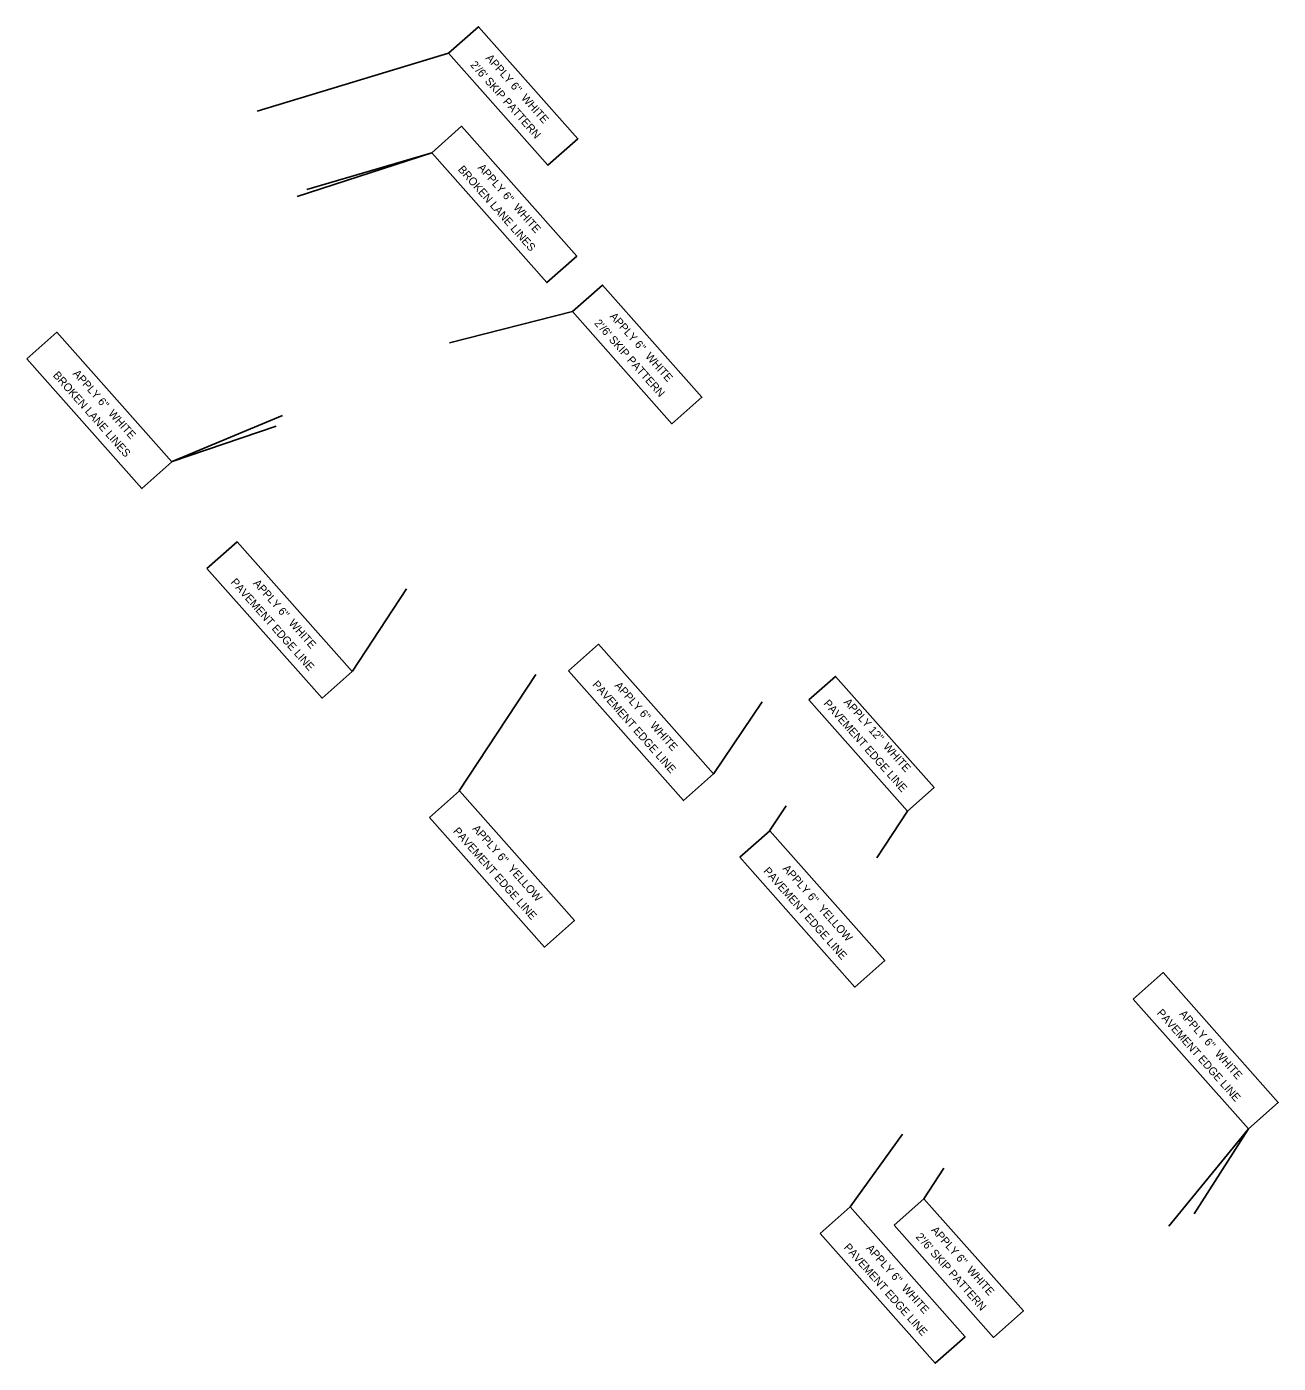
# Model space of a CAD drawing. Extents: x 1966013 to 1974896, y 789499 to 804826.
# Drawn here: x 1971477 to 1972728, y 802536 to 803873 of the extents above; entities that cross this region are included whole.
import ezdxf

# ---------------------------------------------------------------- set-up
doc = ezdxf.new("R2010")
doc.units = 0
doc.layers.add('RD_EX_H2O_BlueLn', color=7, linetype='Continuous')

msp = doc.modelspace()

# ---------------------------------------------------------------- linework, layer by layer
at = {"layer": 'RD_EX_H2O_BlueLn'}
for p, q in [((1971707.3, 803788.2), (1971898.4, 803846)), ((1971747.1, 803702.7), (1971881.6, 803746.4)), ((1971756.8, 803709.9), (1971881.6, 803746.4)), ((1971899.3, 803556.5), (1972022.3, 803587.7)), ((1971622.2, 803437.9), (1971732.6, 803483.8)), ((1971622.2, 803437.9), (1971726.1, 803473.3)), ((1971802.4, 803228.2), (1971856.4, 803310.5)), ((1971909.1, 803108.6), (1971985.6, 803225.1)), ((1972212, 803197.7), (1972163.7, 803125.9)), ((1972235.9, 803093.5), (1972219.3, 803068.8)), ((1972326.5, 803041.7), (1972357.2, 803088.3)), ((1972299.7, 802692.6), (1972352.1, 802765.5)), ((1972618.3, 802673.5), (1972697.8, 802770.6)), ((1972643.8, 802685.7), (1972697.8, 802770.6)), ((1972373.5, 802700.9), (1972393.6, 802731.4))]:
    msp.add_line(p, q, dxfattribs=at)
for points in [[(1971898.4, 803846), (1971997.8, 803734), (1972027.7, 803760.5), (1971928.3, 803872.6)], [(1971881.6, 803746.4), (1971996.6, 803616.8), (1972026.5, 803643.3), (1971911.5, 803773)], [(1972022.3, 803587.7), (1972121.7, 803475.6), (1972151.7, 803502.2), (1972052.3, 803614.2)], [(1971476.8, 803540.6), (1971591.9, 803410.9), (1971621.8, 803437.4), (1971506.8, 803567.1)], [(1971657, 803331), (1971772, 803201.3), (1971802, 803227.8), (1971687, 803357.5)], [(1972018.4, 803228.6), (1972133.4, 803098.9), (1972163.3, 803125.5), (1972048.3, 803255.2)], [(1972258.6, 803199.5), (1972357.2, 803088.3), (1972383.7, 803111.9), (1972285.2, 803223)], [(1971879.3, 803082), (1971994.3, 802952.4), (1972024.2, 802978.9), (1971909.2, 803108.6)], [(1972189.4, 803042.2), (1972304.4, 802912.5), (1972334.4, 802939), (1972219.4, 803068.7)], [(1972582.7, 802900.3), (1972697.8, 802770.6), (1972727.7, 802797.2), (1972612.7, 802926.9)], [(1972343.7, 802674.3), (1972443, 802562.2), (1972473, 802588.8), (1972373.6, 802700.8)], [(1972269.8, 802666), (1972384.8, 802536.4), (1972414.7, 802562.9), (1972299.7, 802692.6)]]:
    msp.add_lwpolyline(points, close=True, dxfattribs=at)

# ---------------------------------------------------------------- texts
for s, height, rotation, p in [("2'/6' SKIP PATTERN", 7.999, 311.5703, (1971919.6, 803834.1)), ("APPLY 6''  WHITE", 7.999, 311.5703, (1971935, 803840.9)), ('BROKEN LANE LINES', 8, 311.5701, (1971907.3, 803729.5)), ("APPLY 6''  WHITE", 8, 311.5701, (1971927.1, 803731.3)), ("APPLY 6''  WHITE", 7.999, 311.5703, (1972059, 803582.6)), ("2'/6' SKIP PATTERN", 7.999, 311.5703, (1972043.6, 803575.8)), ('BROKEN LANE LINES', 8, 311.5701, (1971502.5, 803523.7)), ("APPLY 6''  WHITE", 8, 311.5701, (1971522.4, 803525.4)), ('PAVEMENT EDGE LINE', 8, 311.5701, (1971680.2, 803316.8)), ("APPLY 6''  WHITE", 8, 311.5701, (1971702.6, 803315.8)), ('PAVEMENT EDGE LINE', 8, 311.5701, (1972041.6, 803214.5)), ("APPLY 6''  WHITE", 8, 311.5701, (1972063.9, 803213.5)), ('PAVEMENT EDGE LINE', 8, 311.5701, (1972272.7, 803195.6)), ("APPLY 12''  WHITE", 8, 311.5701, (1972292.9, 803196.9)), ("APPLY 6''  YELLOW", 8, 311.5701, (1971921.7, 803070.4)), ('PAVEMENT EDGE LINE', 8, 311.5701, (1971902.5, 803067.9)), ('PAVEMENT EDGE LINE', 8, 311.5701, (1972212.6, 803028.1)), ("APPLY 6''  YELLOW", 8, 311.5701, (1972231.8, 803030.5)), ('PAVEMENT EDGE LINE', 8, 311.5701, (1972605.9, 802886.2)), ("APPLY 6''  WHITE", 8, 311.5701, (1972628.3, 802885.2)), ("APPLY 6''  WHITE", 7.999, 311.5703, (1972380.3, 802669.1)), ("2'/6' SKIP PATTERN", 7.999, 311.5703, (1972364.9, 802662.4)), ('PAVEMENT EDGE LINE', 8, 311.5701, (1972293, 802651.9)), ("APPLY 6''  WHITE", 8, 311.5701, (1972315.3, 802650.9))]:
    msp.add_text(s, height=height, rotation=rotation, dxfattribs=at).set_placement(p)

doc.saveas('drawing.dxf')
